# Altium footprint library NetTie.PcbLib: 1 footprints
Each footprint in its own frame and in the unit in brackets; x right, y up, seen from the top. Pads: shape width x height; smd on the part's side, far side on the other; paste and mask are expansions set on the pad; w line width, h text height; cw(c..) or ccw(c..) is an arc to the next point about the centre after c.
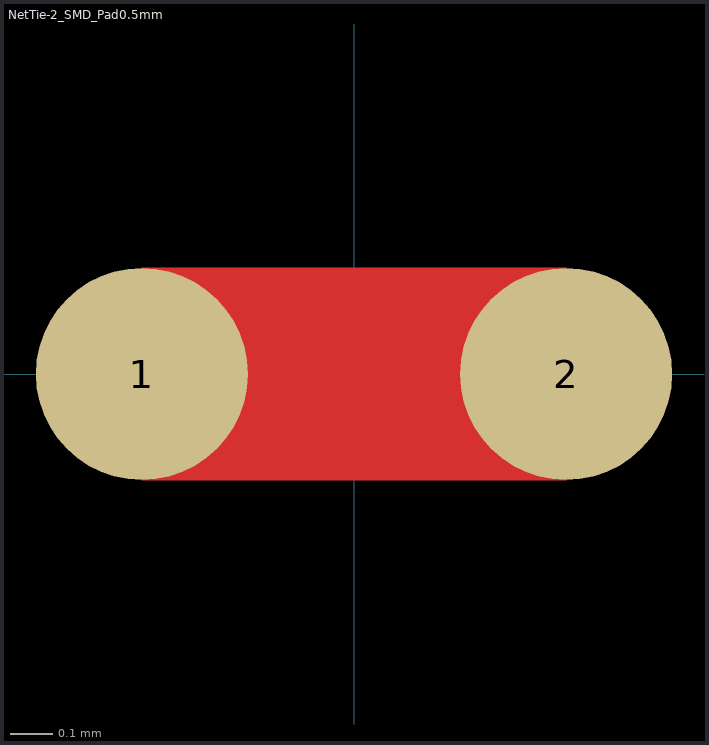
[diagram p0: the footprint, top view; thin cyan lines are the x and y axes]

## NetTie-2_SMD_Pad0.5mm [mm]
pads (2):
  round 0.5 smd: 1(-0.5,0) 2(0.5,0)
F.Cu:
  region: 0.5,-0.25 -0.5,-0.25 -0.5,0.25 0.5,0.25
